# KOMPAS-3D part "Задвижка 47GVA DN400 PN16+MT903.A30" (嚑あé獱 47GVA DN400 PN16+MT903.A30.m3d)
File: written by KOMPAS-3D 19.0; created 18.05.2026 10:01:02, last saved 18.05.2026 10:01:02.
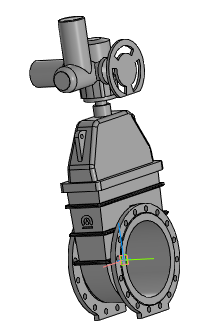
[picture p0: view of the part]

Document properties: Автор: Энергия; Полное имя файла: ..\Задвижка 47GVA DN50_DN1000+MT903.A\Задвижка 47GVA DN400 PN16+MT903.A30.a3d

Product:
- Part/product: Задвижка 47GVA DN400 PN16+MT903.A30
    Масса: 764.396
  - Body: Электропривод МТ903.А30 без блока управления
      Масса: 163.268
  - Body: Задвижка 47GVA DN400 PN16 без исполнительного механизма
      Масса: 601.128

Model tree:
1. Операция без истории:1
2. Операция без истории:2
